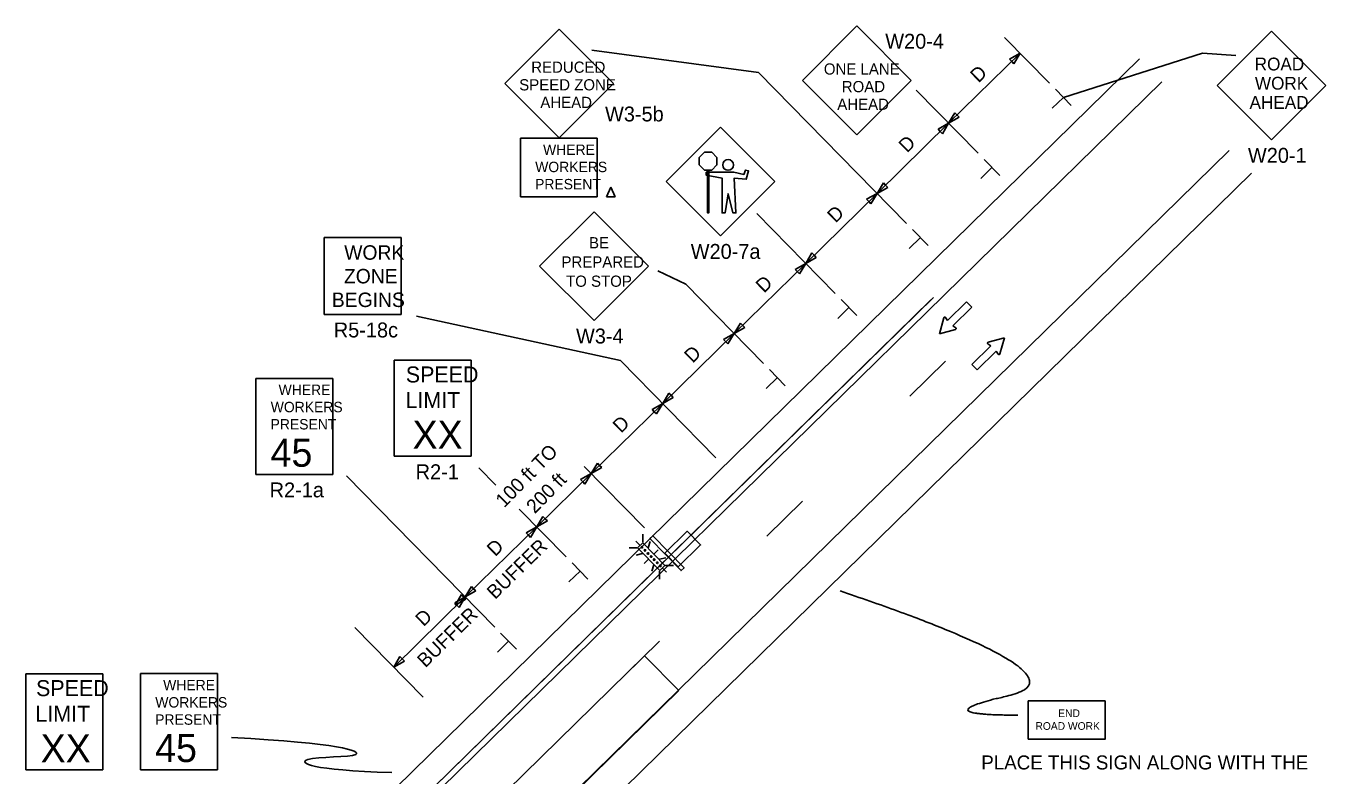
# Model space of a CAD drawing. Extents: x 16735 to 19510, y 5880 to 6929.
# Drawn here: x 16763 to 17412, y 6555 to 6929 of the extents above; entities that cross this region are included whole.
import ezdxf

# ---------------------------------------------------------------- set-up
doc = ezdxf.new("R2010")
doc.units = 0
for name, color, linetype in [('ALI_LEGAL_EX', 7, 'Continuous'), ('BORDER', 7, 'Continuous'), ('MT_SCRATCH_LEVEL_E', 7, 'Continuous'), ('SCRATCH_LEVEL_A', 7, 'Continuous'), ('TRAFFIC_SIGNS_PR', 7, 'Continuous')]:
    doc.layers.add(name, color=color, linetype=linetype)

msp = doc.modelspace()

# ---------------------------------------------------------------- linework, layer by layer
at = {"layer": 'ALI_LEGAL_EX'}
msp.add_line((16866.49, 6450.99), (17215.7, 6793.27), dxfattribs=at)
at = {"layer": 'BORDER'}
for p, q in [((16897.83, 6500.06), (17318.59, 6912.48)), ((17329.79, 6901.05), (16909.03, 6488.64)), ((17363.39, 6866.77), (16942.75, 6454.47)), ((17374.59, 6855.35), (16953.19, 6442.3)), ((16867.78, 6452.26), (17214.45, 6792.05))]:
    msp.add_line(p, q, dxfattribs=at)
for points in [[(17203.89, 6744.04), (17221.74, 6761.54)], [(17132.47, 6674.04), (17150.33, 6691.54)], [(17061.06, 6604.05), (17078.91, 6621.55)]]:
    msp.add_lwpolyline(points, dxfattribs=at)
msp.add_lwpolyline([(17088.53, 6596.94), (17071.47, 6614.35), (17002.57, 6546.82), (17019.63, 6529.42)], close=True, dxfattribs=at)
at = {"layer": 'MT_SCRATCH_LEVEL_E'}
for p, q in [((17232.26, 6791.1), (17222.79, 6781.82)), ((17232.26, 6791.1), (17222.79, 6781.82)), ((17225.41, 6779.15), (17234.87, 6788.43)), ((17225.41, 6779.15), (17234.87, 6788.43)), ((17234.87, 6788.43), (17232.26, 6791.1)), ((17234.87, 6788.43), (17232.26, 6791.1)), ((17220.94, 6783.18), (17218.68, 6775.15)), ((17220.94, 6783.18), (17218.68, 6775.15)), ((17222.79, 6781.82), (17221.77, 6783.31)), ((17222.79, 6781.82), (17221.77, 6783.31)), ((17226.88, 6778.1), (17225.41, 6779.15)), ((17226.88, 6778.1), (17225.41, 6779.15)), ((17218.68, 6775.15), (17226.72, 6777.28)), ((17218.68, 6775.15), (17226.72, 6777.28)), ((17251.12, 6773.1), (17243.07, 6770.97)), ((17251.12, 6773.1), (17243.07, 6770.97)), ((17248.85, 6765.07), (17251.12, 6773.1)), ((17248.85, 6765.07), (17251.12, 6773.1)), ((17244.39, 6769.1), (17234.92, 6759.82)), ((17244.39, 6769.1), (17234.92, 6759.82)), ((17237.54, 6757.15), (17247.01, 6766.42)), ((17237.54, 6757.15), (17247.01, 6766.42)), ((17242.92, 6770.15), (17244.39, 6769.1)), ((17242.92, 6770.15), (17244.39, 6769.1)), ((17247.01, 6766.42), (17248.03, 6764.94)), ((17247.01, 6766.42), (17248.03, 6764.94)), ((17234.92, 6759.82), (17237.54, 6757.15)), ((17234.92, 6759.82), (17237.54, 6757.15))]:
    msp.add_line(p, q, dxfattribs=at)
for centre, start, end in [((17221.39, 6783.04), 34.46189, 164.19881), ((17221.39, 6783.04), 34.46189, 164.19881), ((17226.6, 6777.73), 284.85054, 54.38951), ((17226.6, 6777.73), 284.85054, 54.38951), ((17243.2, 6770.52), 104.85054, 234.38951), ((17243.2, 6770.52), 104.85054, 234.38951), ((17248.4, 6765.21), 214.46189, 344.19881), ((17248.4, 6765.21), 214.46189, 344.19881)]:
    msp.add_arc(centre, 0.463, start, end, dxfattribs=at)
at = {"layer": 'SCRATCH_LEVEL_A'}
for p, q in [((17177.39, 6928.9), (17150.24, 6901.75)), ((17204.54, 6901.75), (17177.39, 6928.9)), ((17028.77, 6927.38), (17001.61, 6900.23)), ((17055.92, 6900.23), (17028.77, 6927.38)), ((17384.6, 6926.32), (17357.45, 6899.16)), ((17411.75, 6899.16), (17384.6, 6926.32)), ((17150.24, 6901.75), (17177.39, 6874.6)), ((17177.39, 6874.6), (17204.54, 6901.75)), ((17001.61, 6900.23), (17028.77, 6873.07)), ((17028.77, 6873.07), (17055.92, 6900.23)), ((17357.45, 6899.16), (17384.6, 6872.01)), ((17384.6, 6872.01), (17411.75, 6899.16)), ((17109.36, 6878.31), (17082.2, 6851.16)), ((17136.51, 6851.16), (17109.36, 6878.31)), ((17009.43, 6872.82), (17047.83, 6872.82)), ((17009.43, 6843.5), (17009.43, 6872.82)), ((17047.83, 6843.5), (17047.83, 6872.82)), ((17082.2, 6851.16), (17109.36, 6824.01)), ((17109.36, 6824.01), (17136.51, 6851.16)), ((17009.43, 6843.5), (17047.83, 6843.5)), ((17046.19, 6836.05), (17019.04, 6808.9)), ((17073.34, 6808.9), (17046.19, 6836.05)), ((16911.42, 6784.77), (16911.42, 6823.17)), ((16911.42, 6823.17), (16949.82, 6823.17)), ((16949.82, 6784.77), (16949.82, 6823.17)), ((17019.04, 6808.9), (17046.19, 6781.74)), ((17046.19, 6781.74), (17073.34, 6808.9)), ((16911.42, 6784.77), (16949.82, 6784.77)), ((16946.44, 6761.96), (16984.84, 6761.96)), ((16946.44, 6713.96), (16946.44, 6761.96)), ((16984.84, 6713.96), (16984.84, 6761.96)), ((16877.34, 6752.87), (16915.74, 6752.87)), ((16877.34, 6704.87), (16877.34, 6752.87)), ((16915.74, 6704.87), (16915.74, 6752.87)), ((16946.44, 6713.96), (16984.84, 6713.96)), ((16877.34, 6704.87), (16915.74, 6704.87)), ((17070.56, 6671.01), (17070.6, 6674.99)), ((17081.53, 6665.61), (17092.67, 6676.53)), ((17099.38, 6669.68), (17092.67, 6676.53)), ((17067.65, 6668.16), (17063.67, 6668.2)), ((17069.11, 6669.58), (17067.13, 6671.6)), ((17070.15, 6668.52), (17070.15, 6668.52)), ((17074.18, 6671.34), (17073.3, 6668.2)), ((17088.24, 6658.76), (17099.38, 6669.68)), ((17070.42, 6665.34), (17067.27, 6664.53)), ((17073.31, 6662.39), (17071.3, 6660.41)), ((17071.67, 6666.97), (17071.67, 6666.97)), ((17073.19, 6665.41), (17073.19, 6665.41)), ((17074.71, 6663.86), (17074.71, 6663.86)), ((17076.22, 6665.23), (17078.23, 6667.21)), ((17076.24, 6662.31), (17076.24, 6662.31)), ((17082.06, 6663.3), (17078.91, 6662.49)), ((17075.99, 6659.66), (17075.11, 6656.52)), ((17077.76, 6660.76), (17077.76, 6660.76)), ((17078.93, 6652.63), (17078.97, 6656.61)), ((17079.28, 6659.2), (17079.28, 6659.2)), ((17080.42, 6658.04), (17082.4, 6656.02)), ((17085.86, 6659.42), (17081.88, 6659.46)), ((16762.5, 6605.28), (16800.9, 6605.28)), ((16762.5, 6557.28), (16762.5, 6605.28)), ((16800.9, 6557.28), (16800.9, 6605.28)), ((16819.7, 6605.37), (16858.1, 6605.37)), ((16819.7, 6557.37), (16819.7, 6605.37)), ((16858.1, 6557.37), (16858.1, 6605.37)), ((16762.5, 6557.28), (16800.9, 6557.28)), ((16819.7, 6557.37), (16858.1, 6557.37))]:
    msp.add_line(p, q, dxfattribs=at)
for points in [[(17101.32, 6865.8), (17104.99, 6865.8), (17107.59, 6863.2), (17107.59, 6859.52), (17104.99, 6856.93), (17101.32, 6856.93), (17098.72, 6859.52), (17098.72, 6863.2)], [(17116.04, 6855.88), (17102.21, 6855.88), (17102.21, 6854.38), (17110.18, 6852.93), (17110.18, 6835.53), (17111.68, 6835.53), (17113.18, 6845.13), (17115.58, 6835.53), (17117.08, 6835.53), (17116.18, 6852.93), (17122.18, 6852.33), (17123.38, 6856.53), (17121.92, 6856.89), (17121.03, 6854.79)], [(17102.86, 6856.93), (17102.86, 6835.55), (17103.45, 6835.55), (17103.45, 6856.93)], [(17088.24, 6658.76), (17081.53, 6665.61), (17092.67, 6676.53), (17099.38, 6669.68)], [(17070.55, 6670.68), (17081.55, 6659.46), (17078.98, 6656.94), (17067.98, 6668.16)], [(17074, 6672.81), (17089.67, 6656.82), (17091.17, 6658.29), (17075.5, 6674.28)], [(17263.04, 6572.57), (17301.44, 6572.57), (17301.44, 6591.77), (17263.04, 6591.77)]]:
    msp.add_lwpolyline(points, close=True, dxfattribs=at)
for points in [[(17054.58, 6848.44), (17052.35, 6843.5)], [(17052.35, 6843.5), (17054.58, 6848.44)], [(17052.35, 6843.5), (17056.82, 6843.5)], [(17056.82, 6843.5), (17052.35, 6843.5)], [(17056.82, 6843.5), (17054.58, 6848.44)], [(17054.58, 6848.44), (17056.82, 6843.5)]]:
    msp.add_lwpolyline(points, dxfattribs=at)
for centre, radius in [((17113.16, 6859.5), 2.7), ((17070.15, 6668.52), 0.379), ((17071.67, 6666.97), 0.379), ((17073.19, 6665.41), 0.379), ((17074.71, 6663.86), 0.379), ((17076.23, 6662.31), 0.379), ((17077.76, 6660.76), 0.379), ((17079.26, 6659.22), 0.379)]:
    msp.add_circle(centre, radius, dxfattribs=at)
msp.add_open_spline([(17257.77, 6584.65), (17210.53, 6584.65), (17295.55, 6604), (17169.11, 6646.71)], degree=2, dxfattribs=at)
at = {"layer": 'TRAFFIC_SIGNS_PR'}
for p, q in [((17273.71, 6900.3), (17251.27, 6923.2)), ((17128.37, 6905.72), (17045.03, 6916.9)), ((17259.01, 6915.3), (17223.3, 6880.3)), ((17253.72, 6912.32), (17259.01, 6915.3)), ((17253.72, 6912.32), (17259.01, 6915.3)), ((17259.01, 6915.3), (17255.92, 6910.07)), ((17259.01, 6915.3), (17255.92, 6910.07)), ((17280.62, 6893.25), (17350.04, 6915.33)), ((17350.04, 6915.33), (17366.75, 6914.19)), ((17254.82, 6911.2), (17253.72, 6912.32)), ((17254.82, 6911.2), (17253.72, 6912.32)), ((17255.92, 6910.07), (17254.82, 6911.2)), ((17255.92, 6910.07), (17254.82, 6911.2)), ((17202.3, 6830.3), (17128.37, 6905.72)), ((17238, 6865.3), (17207.1, 6896.83)), ((17276.68, 6897.27), (17284.56, 6889.23)), ((17280.62, 6893.25), (17275.06, 6887.8)), ((17223.3, 6880.3), (17226.39, 6885.52)), ((17223.3, 6880.3), (17226.39, 6885.52)), ((17228.59, 6883.28), (17223.3, 6880.3)), ((17228.59, 6883.28), (17223.3, 6880.3)), ((17226.39, 6885.52), (17227.49, 6884.4)), ((17226.39, 6885.52), (17227.49, 6884.4)), ((17227.49, 6884.4), (17228.59, 6883.28)), ((17227.49, 6884.4), (17228.59, 6883.28)), ((17223.3, 6880.3), (17187.59, 6845.3)), ((17218.01, 6877.32), (17223.3, 6880.3)), ((17218.01, 6877.32), (17223.3, 6880.3)), ((17219.11, 6876.2), (17218.01, 6877.32)), ((17219.11, 6876.2), (17218.01, 6877.32)), ((17220.21, 6875.07), (17219.11, 6876.2)), ((17220.21, 6875.07), (17219.11, 6876.2)), ((17223.3, 6880.3), (17220.21, 6875.07)), ((17223.3, 6880.3), (17220.21, 6875.07)), ((17244.91, 6858.25), (17239.35, 6852.8)), ((17240.98, 6862.27), (17248.85, 6854.23)), ((17187.59, 6845.3), (17190.68, 6850.53)), ((17187.59, 6845.3), (17190.68, 6850.53)), ((17190.68, 6850.53), (17191.78, 6849.4)), ((17190.68, 6850.53), (17191.78, 6849.4)), ((17187.59, 6845.3), (17151.89, 6810.3)), ((17182.31, 6842.32), (17187.59, 6845.3)), ((17182.31, 6842.32), (17187.59, 6845.3)), ((17187.59, 6845.3), (17184.51, 6840.07)), ((17187.59, 6845.3), (17184.51, 6840.07)), ((17192.88, 6848.28), (17187.59, 6845.3)), ((17192.88, 6848.28), (17187.59, 6845.3)), ((17191.78, 6849.4), (17192.88, 6848.28)), ((17191.78, 6849.4), (17192.88, 6848.28)), ((17183.41, 6841.2), (17182.31, 6842.32)), ((17183.41, 6841.2), (17182.31, 6842.32)), ((17184.51, 6840.07), (17183.41, 6841.2)), ((17184.51, 6840.07), (17183.41, 6841.2)), ((17166.59, 6795.3), (17127.5, 6835.18)), ((17205.27, 6827.27), (17213.14, 6819.23)), ((17209.2, 6823.25), (17203.64, 6817.8)), ((17151.89, 6810.3), (17154.97, 6815.53)), ((17157.17, 6813.28), (17151.89, 6810.3)), ((17154.97, 6815.53), (17156.07, 6814.4)), ((17156.07, 6814.4), (17157.17, 6813.28)), ((17092.11, 6799.86), (17078.08, 6806.61)), ((17151.89, 6810.3), (17116.18, 6775.3)), ((17146.6, 6807.32), (17151.89, 6810.3)), ((17146.6, 6807.32), (17151.89, 6810.3)), ((17147.7, 6806.2), (17146.6, 6807.32)), ((17147.7, 6806.2), (17146.6, 6807.32)), ((17148.8, 6805.08), (17147.7, 6806.2)), ((17148.8, 6805.08), (17147.7, 6806.2)), ((17151.89, 6810.3), (17148.8, 6805.08)), ((17151.89, 6810.3), (17148.8, 6805.08)), ((17130.88, 6760.3), (17092.11, 6799.86)), ((17169.56, 6792.27), (17177.43, 6784.23)), ((17173.5, 6788.25), (17167.94, 6782.8)), ((17059.43, 6761.77), (16957.46, 6783.94)), ((17116.18, 6775.3), (17119.26, 6780.53)), ((17116.18, 6775.3), (17119.26, 6780.53)), ((17121.46, 6778.28), (17116.18, 6775.3)), ((17121.46, 6778.28), (17116.18, 6775.3)), ((17119.26, 6780.53), (17120.36, 6779.41)), ((17119.26, 6780.53), (17120.36, 6779.41)), ((17120.36, 6779.41), (17121.46, 6778.28)), ((17120.36, 6779.41), (17121.46, 6778.28)), ((17116.18, 6775.3), (17080.47, 6740.3)), ((17110.89, 6772.32), (17116.18, 6775.3)), ((17110.89, 6772.32), (17116.18, 6775.3)), ((17111.99, 6771.2), (17110.89, 6772.32)), ((17111.99, 6771.2), (17110.89, 6772.32)), ((17116.18, 6775.3), (17113.09, 6770.08)), ((17116.18, 6775.3), (17113.09, 6770.08)), ((17113.09, 6770.08), (17111.99, 6771.2)), ((17113.09, 6770.08), (17111.99, 6771.2)), ((17107.04, 6713.19), (17059.43, 6761.77)), ((17137.79, 6753.25), (17132.23, 6747.8)), ((17133.85, 6757.27), (17141.73, 6749.23)), ((17080.47, 6740.3), (17044.76, 6705.3)), ((17075.18, 6737.32), (17080.47, 6740.3)), ((17075.18, 6737.32), (17080.47, 6740.3)), ((17080.47, 6740.3), (17077.38, 6735.08)), ((17080.47, 6740.3), (17077.38, 6735.08)), ((17080.47, 6740.3), (17083.56, 6745.53)), ((17080.47, 6740.3), (17083.56, 6745.53)), ((17085.76, 6743.28), (17080.47, 6740.3)), ((17085.76, 6743.28), (17080.47, 6740.3)), ((17083.56, 6745.53), (17084.66, 6744.41)), ((17083.56, 6745.53), (17084.66, 6744.41)), ((17084.66, 6744.41), (17085.76, 6743.28)), ((17084.66, 6744.41), (17085.76, 6743.28)), ((17076.28, 6736.2), (17075.18, 6737.32)), ((17076.28, 6736.2), (17075.18, 6737.32)), ((17077.38, 6735.08), (17076.28, 6736.2)), ((17077.38, 6735.08), (17076.28, 6736.2)), ((16997.19, 6699.49), (16988.74, 6708.12)), ((17071.33, 6678.19), (17041.26, 6708.87)), ((17044.76, 6705.3), (17047.85, 6710.53)), ((17044.76, 6705.3), (17047.85, 6710.53)), ((17050.05, 6708.29), (17044.76, 6705.3)), ((17050.05, 6708.29), (17044.76, 6705.3)), ((17047.85, 6710.53), (17048.95, 6709.41)), ((17047.85, 6710.53), (17048.95, 6709.41)), ((17048.95, 6709.41), (17050.05, 6708.29)), ((17048.95, 6709.41), (17050.05, 6708.29)), ((16996.59, 6628.67), (16922.65, 6704.12)), ((17044.76, 6705.3), (17017.6, 6678.68)), ((17039.48, 6702.32), (17044.76, 6705.3)), ((17039.48, 6702.32), (17044.76, 6705.3)), ((17040.58, 6701.2), (17039.48, 6702.32)), ((17040.58, 6701.2), (17039.48, 6702.32)), ((17041.67, 6700.08), (17040.58, 6701.2)), ((17041.67, 6700.08), (17040.58, 6701.2)), ((17044.76, 6705.3), (17041.67, 6700.08)), ((17044.76, 6705.3), (17041.67, 6700.08)), ((17032.3, 6663.68), (17008.83, 6687.62)), ((17017.6, 6678.68), (17020.68, 6683.9)), ((17022.88, 6681.66), (17017.6, 6678.68)), ((17020.68, 6683.9), (17021.78, 6682.78)), ((17021.78, 6682.78), (17022.88, 6681.66)), ((17017.6, 6678.68), (16981.89, 6643.68)), ((17012.31, 6675.69), (17017.6, 6678.68)), ((17012.31, 6675.69), (17017.6, 6678.68)), ((17013.41, 6674.57), (17012.31, 6675.69)), ((17013.41, 6674.57), (17012.31, 6675.69)), ((17014.51, 6673.45), (17013.41, 6674.57)), ((17014.51, 6673.45), (17013.41, 6674.57)), ((17017.6, 6678.68), (17014.51, 6673.45)), ((17017.6, 6678.68), (17014.51, 6673.45)), ((17039.2, 6656.63), (17033.64, 6651.18)), ((17035.27, 6660.65), (17043.14, 6652.61)), ((16981.89, 6643.68), (16984.97, 6648.9)), ((16984.97, 6648.9), (16986.07, 6647.78)), ((16981.89, 6643.68), (16946.18, 6608.68)), ((16976.6, 6640.69), (16981.89, 6643.68)), ((16976.6, 6640.69), (16981.89, 6643.68)), ((16976.85, 6639.65), (16979.94, 6644.87)), ((16982.14, 6642.63), (16976.85, 6639.65)), ((16981.89, 6643.68), (16978.8, 6638.45)), ((16981.89, 6643.68), (16978.8, 6638.45)), ((16979.94, 6644.87), (16981.04, 6643.75)), ((16981.04, 6643.75), (16982.14, 6642.63)), ((16987.17, 6646.66), (16981.89, 6643.68)), ((16986.07, 6647.78), (16987.17, 6646.66)), ((16977.7, 6639.57), (16976.6, 6640.69)), ((16977.7, 6639.57), (16976.6, 6640.69)), ((16978.8, 6638.45), (16977.7, 6639.57)), ((16978.8, 6638.45), (16977.7, 6639.57)), ((16960.88, 6593.68), (16926.81, 6628.44)), ((16999.56, 6625.64), (17007.44, 6617.61)), ((17003.5, 6621.63), (16997.94, 6616.18)), ((16946.18, 6608.68), (16949.27, 6613.9)), ((16946.18, 6608.68), (16949.27, 6613.9)), ((16951.47, 6611.66), (16946.18, 6608.68)), ((16951.47, 6611.66), (16946.18, 6608.68)), ((16949.27, 6613.9), (16950.37, 6612.78)), ((16949.27, 6613.9), (16950.37, 6612.78)), ((16950.37, 6612.78), (16951.47, 6611.66)), ((16950.37, 6612.78), (16951.47, 6611.66))]:
    msp.add_line(p, q, dxfattribs=at)
msp.add_open_spline([(16945.2, 6556.01), (16904.44, 6557.07), (16892.05, 6564.72), (16940.7, 6562.76), (16919.31, 6570.63), (16865.19, 6573.49)], degree=3, dxfattribs=at)

# ---------------------------------------------------------------- texts
at = {"layer": 'SCRATCH_LEVEL_A'}
for s, height, p in [('W20-4', 7.44, (17191.64, 6917.56)), ('REDUCED', 5.6, (17014.82, 6905.53)), ('ONE LANE', 5.6, (17160.97, 6904.62)), ('ROAD', 6.4, (17376.14, 6906.7)), ('SPEED ZONE', 5.6, (17008.82, 6896.73)), ('WORK', 6.4, (17376.25, 6897.1)), ('ROAD', 5.6, (17169.92, 6895.82)), ('AHEAD', 5.6, (17019.38, 6887.93)), ('W3-5b', 7.44, (17051.69, 6881.22)), ('AHEAD', 5.6, (17167.68, 6887.02)), ('AHEAD', 6.4, (17373.56, 6887.5)), ('WHERE', 5.2, (17020.74, 6864.5)), ('W20-1', 7.44, (17372.77, 6860.57)), ('WORKERS', 5.2, (17016.82, 6855.9)), ('PRESENT', 5.2, (17016.75, 6847.3)), ('WORK', 7.217, (16921.42, 6812.14)), ('BE', 5.6, (17043.69, 6817.82)), ('W20-7a', 7.44, (17094.49, 6812.57)), ('PREPARED', 5.6, (17029.93, 6808.22)), ('ZONE', 7.217, (16921.3, 6800.33)), ('TO STOP', 5.6, (17032.21, 6798.62)), ('BEGINS', 7.217, (16915.23, 6788.52)), ('R5-18c', 7.44, (16916.23, 6773.33)), ('W3-4', 7.44, (17037.19, 6770.3)), ('SPEED', 8, (16952.2, 6750.82)), ('WHERE', 5.2, (16888.65, 6744.56)), ('LIMIT', 8, (16952.04, 6738.02)), ('WORKERS', 5.2, (16884.72, 6735.96)), ('PRESENT', 5.2, (16884.65, 6727.36)), ('XX', 14.031, (16955.55, 6717.71)), ('45', 14.031, (16884.64, 6708.73)), ('R2-1', 7.44, (16957.11, 6702.52)), ('R2-1a', 7.44, (16884.19, 6693.43)), ('SPEED', 8, (16767.53, 6594.14)), ('WHERE', 5.2, (16831.01, 6597.05)), ('WORKERS', 5.2, (16827.08, 6588.45)), ('LIMIT', 8, (16767.2, 6581.34)), ('PRESENT', 5.2, (16827.01, 6579.85)), ('END', 3.831, (17278.04, 6583.7)), ('ROAD WORK', 3.831, (17266.65, 6577.31)), ('XX', 14.031, (16769.81, 6561.04)), ('45', 14.031, (16827, 6561.22)), ('PLACE THIS SIGN ALONG WITH THE', 7, (17239.59, 6557.5))]:
    msp.add_text(s, height=height, dxfattribs=at).set_placement(p)
at = {"layer": 'TRAFFIC_SIGNS_PR'}
for s, rotation, p in [('D', 44.43273, (17238.21, 6900.19)), ('D', 44.43273, (17202.51, 6865.19)), ('D', 44.43273, (17166.81, 6830.18)), ('D', 44.43273, (17131.1, 6795.18)), ('D', 44.43273, (17095.4, 6760.18)), ('D', 44.43273, (17059.69, 6725.18)), ('100 ft TO', 45.6, (17001.3, 6687.88)), ('200 ft', 45.6, (17016.62, 6684.94)), ('BUFFER', 44.43273, (16996.78, 6642.12)), ('D', 44.43273, (16996.81, 6663.56)), ('D', 44.43273, (16961.1, 6628.56)), ('BUFFER', 44.43273, (16962, 6608.01))]:
    msp.add_text(s, height=7, rotation=rotation, dxfattribs=at).set_placement(p)

doc.saveas('drawing.dxf')
